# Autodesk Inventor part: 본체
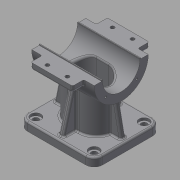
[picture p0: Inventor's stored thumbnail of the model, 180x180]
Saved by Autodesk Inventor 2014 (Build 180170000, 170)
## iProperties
Created: 2015-12
Part Number: 본체
Material: 알루미늄 6061
Document SubType Name: Modeling
Designer: mduedu
Density: 2.71 g/cm^3
Appearance: 알루미늄 - 평지
Mass: 475.396 g
Surface Area: 479.255 cm^2
Volume: 175.423 cm^3
Author: mduedu
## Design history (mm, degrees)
sketch "스케치1"
  geometry: L1 (45, 40)-(-45, 40); L2 (-45, 40)-(-45, -40); L3 (-45, -40)-(45, -40); L4 (45, -40)-(45, 40); L5 (45, 40)-(-45, -40); L6 (-45, 40)-(45, -40); 1 further point
  constraints: 12 end point, 2 midpoint, 2 parallel, 1 horizontal, 1 perpendicular
  dimensions: "d0" = 90 distance of L2.end L3.end; "d2" = 80 distance of L1.end L2.end
extrude "돌출1" new body sketch "스케치1" distance "d3" = 10; taper "d4" = 0 deg
sketch "스케치2"
  geometry: L1 (0, 40)-(0, -40) reference; C1 r 32.5 at (80, 0); 1 further point
  constraints: 1 centre point
  dimensions: "d5" = 65 diameter of C1; "d6" = 80 distance from line of C1.centre L1
extrude "돌출2" join sketch "스케치2" stored distance "d7" = 75; taper "d8" = 0 deg
sketch "스케치3"
  geometry: L1 (-27.5, -20)-(27.5, -20); L2 (27.5, -20)-(27.5, 20); L3 (27.5, 20)-(-27.5, 20); L4 (-27.5, 20)-(-27.5, -20); L5 (-27.5, -20)-(27.5, 20); L6 (27.5, -20)-(-27.5, 20); 1 further point
  constraints: 12 end point, 2 midpoint, 2 parallel, 1 horizontal, 1 perpendicular
  dimensions: "d9" = 55 distance of L2.end L3.end; "d11" = 40 distance of L1.end L2.end
extrude "돌출3" new body sketch "스케치3" stored distance "d12" = 75; taper "d13" = 0 deg
fillet "모깎기1"
fillet "모깎기2"
feature "결합1"
  node "솔리드2"
fillet "모깎기3" dims "d14" = 10
sketch "스케치4"
  geometry: L1 (-37.5, 47.5)-(37.5, 47.5) reference; L2 (35, 10)-(45, 10) reference; L3 (32.5, 47.5)-(40, 10); L4 (37.5, 47.5)-(37.5, 112.5) reference; L5 (45, 10)-(45, 0) reference; 1 further point
  constraints: 2 end point, 1 midpoint, 1 point on line
  dimensions: "d15" = 5 distance from line of L3.start L4; "d16" = 5 distance from line of L3.end L5
sketch "스케치5"
  geometry: L1 (10, 40)-(10, 30) reference; L2 (10, 35)-(56.569, 22.522); L3 (0, 40)-(10, 40) reference; 2 further points
  constraints: 2 end point, 1 midpoint, 2 other
  dimensions: "d17" = 5 distance from line of L2.start L3; "d18" = 15 deg angle of L2 L3
feature "리브1" dims "d19" = 1, "d20" = 6, "d21" = 0, "d22" = 0, "d23" = 1, "d24" = 1
feature "리브2" dims "d25" = 1, "d26" = 6, "d27" = 0, "d28" = 0, "d29" = 1, "d30" = 1
fillet "모깎기4" dims "d31" = 2
fillet "모깎기5" dims "d32" = 2
fillet "모깎기6" dims "d33" = 2
sketch "스케치6"
  geometry: A1 r 10 centre (-35, 30) between (-35, 40) and (-45, 30) reference; A2 r 10 centre (35, 30) between (45, 30) and (35, 40) reference; A3 r 10 centre (35, -30) between (35, -40) and (45, -30) reference; A4 r 10 centre (-35, -30) between (-45, -30) and (-35, -40) reference; 5 further points
  constraints: 4 coincident
hole "구멍1" sketch "스케치6" at (-35, 30), (35, 30), (35, -30), (-35, -30) diameter "d34" = 7; stored, may be unused: countersink angle "d38" = 90 deg, drill point angle "d40" = 118 deg; dims "d35" = 6, "d36" = 12, "d37" = 3, "d39" = 8
fillet "모깎기7" dims "d41" = 2
hole "구멍2" diameter "d44" = 45; stored, may be unused: countersink angle "d48" = 90 deg, drill point angle "d50" = 118 deg; dims "d42" = 10, "d43" = 10, "d45" = 6, "d46" = 4, "d47" = 2, "d49" = 8
sketch "스케치7" dims "d52" = 26.5
  geometry: L1 (0, 0)-(32.5, 0); L2 (0, 0)-(22.981, 22.981); A1 r 32.5 centre (0, 0) between (32.5, 0) and (22.981, 22.981) reference; 3 further points
  constraints: 4 end point, 2 point on circle, 1 coincident, 1 horizontal, 1 point on line, 3 other
  dimensions: "d51" = 45 deg angle of L2 L1
hole "구멍3" sketch "스케치7" at (18.738, 18.738) diameter "d54" = 2.459; stored, may be unused: countersink angle "d58" = 90 deg, drill point angle "d60" = 118 deg; dims "d55" = 8, "d56" = 4, "d57" = 2, "d59" = 10
sketch "스케치8"
  geometry: L1 (72.5, 31.623)-(72.5, 46); L2 (72.5, 46)-(87.5, 46); L3 (87.5, 46)-(87.5, 31.623); A1 r 32.5 centre (80, 0) between (87.5, 31.623) and (72.5, 31.623) reference; 2 further points
  constraints: 6 end point, 2 point on circle, 1 midpoint, 1 parallel, 1 vertical, 1 vertical alignment
  dimensions: "d64" = 15 distance of L1.end L2.end; "d66" = 46 distance from line of L2 A1.centre
extrude "돌출4" join sketch "스케치8" stored distance "d67" = 50; taper "d68" = 0 deg
fillet "모깎기8" dims "d69" = 3
fillet "모깎기9" dims "d70" = 2
sketch "스케치9"
  geometry: L1 (-76, 82.5)-(76, 82.5); L2 (76, 82.5)-(76, 0); L3 (76, 0)-(-76, 0); L4 (-76, 0)-(-76, 82.5); L5 (-46, 4.5)-(-46, -4.5) reference; C1 r 32.5 at (0, 0) reference; 2 further points
  constraints: 8 end point, 2 parallel, 1 coincident, 1 horizontal, 1 midpoint, 1 perpendicular
  dimensions: "d71" = 50 distance edge to line of C1 L1; "d72" = 30 distance between parallel lines of L4 L5
extrude "돌출5" cut sketch "스케치9" stored distance "d73" = 0; taper "d74" = 0 deg
node "작업 평면1"
sketch "스케치10"
  geometry: L1 (-7.5, 15)-(7.5, 15); L2 (-7.5, -15)-(7.5, -15); A1 r 20 centre (-7.5, 0) between (-7.5, 20) and (-26.977, 4.545) reference; A2 r 20 centre (7.5, 0) between (26.977, 4.545) and (7.5, 20) reference; A3 r 15 centre (-7.5, 0) between (-7.5, 15) and (-7.5, -15); A4 r 15 centre (7.5, 0) between (7.5, -15) and (7.5, 15); 1 further point
  constraints: 7 point on circle, 4 end point, 4 tangent, 3 point on line, 2 centre point, 2 coincident, 1 horizontal
  dimensions: "d77" = 5 radial gap between concentric circles of A3 A1
extrude "돌출6" cut sketch "스케치10" stored distance "d78" = 50; taper "d79" = 0 deg
fillet "모깎기10" dims "d80" = 3
sketch "스케치11"
  geometry: 2 further points
  constraints: 1 coincident
hole "구멍4" sketch "스케치11" at (0, 0) diameter "d81" = 12; stored, may be unused: countersink angle "d85" = 90 deg, drill point angle "d87" = 118 deg; dims "d82" = 8, "d83" = 40, "d84" = 10, "d86" = 10
sketch "스케치12"
  geometry: C1 r 10 at (0, 0); 1 further point
  constraints: 1 centre point, 1 coincident
  dimensions: "d88" = 20 diameter of C1
extrude "돌출7" cut sketch "스케치12" distance "d89" = 5; taper "d90" = 0 deg
chamfer "모따기1" distance "d91" = 1; stored, may be unused: second distance "d92" = 2, angle "d93" = 45 deg
fillet "모깎기11" dims "d94" = 0.5
feature "립1" dims "d95" = 1, "d96" = 1, "d97" = 0, "d98" = 3 deg, "d99" = 3 deg, "d100" = 0
sketch "스케치13"
  geometry: 4 further points
hole "구멍5" sketch "스케치13" at (34, 5.936), (10, -72.269), (34, -72.269), (10, 5.936) diameter "d101" = 4.5; stored, may be unused: countersink angle "d105" = 90 deg, drill point angle "d107" = 0 deg; dims "d102" = 6, "d103" = 4, "d104" = 2, "d106" = 8
fillet "모깎기12" dims "d115" = 0.3
node "솔리드1"
mirror "대칭1"
mirror "대칭2"
pattern_circular "원형 패턴1" dims angle "d62" = 360 deg
mirror "대칭3"
mirror "대칭4"
